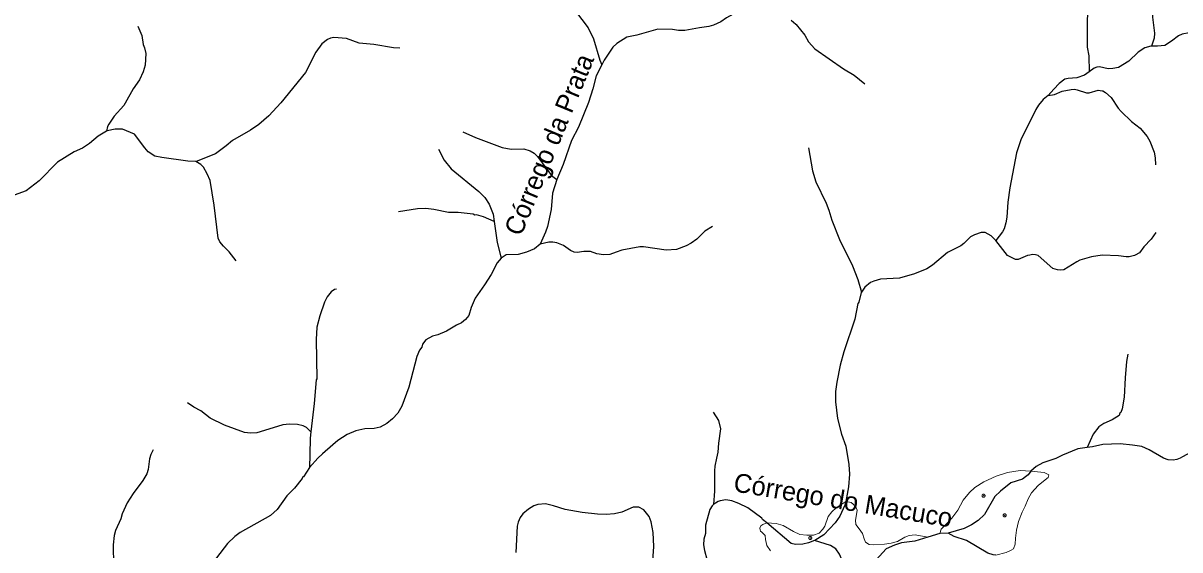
# Model space of a CAD drawing. Extents: x 396 to 422.2, y 7649.8 to 7677.6.
# Drawn here: x 409.11 to 415.26, y 7656.16 to 7658.96 of the extents above; entities that cross this region are included whole.
import ezdxf
from ezdxf.enums import TextEntityAlignment as Align

# ---------------------------------------------------------------- set-up
doc = ezdxf.new("R2010")
doc.units = 0
doc.header["$LTSCALE"] = 0.032
doc.header["$PDMODE"] = 32
doc.header["$PDSIZE"] = 0.016
doc.linetypes.add('SHORT_DASHED', pattern=[2.7, 1.5, -1.2])
doc.layers.add('21', color=7, linetype='SHORT_DASHED', lineweight=13)
doc.layers.add('7', color=7, linetype='Continuous', lineweight=25)
doc.layers.add('61', color=7, linetype='Continuous')

msp = doc.modelspace()

# ---------------------------------------------------------------- linework, layer by layer
at = {"layer": '21'}
for points in [[(413.9857, 7656.2498), (413.9939, 7656.2718), (414.0154, 7656.2949), (414.05, 7656.3312), (414.0814, 7656.3742), (414.1095, 7656.427), (414.1442, 7656.4666), (414.1722, 7656.4947), (414.2201, 7656.5244), (414.2862, 7656.5541), (414.3456, 7656.574), (414.4133, 7656.5839), (414.4702, 7656.5802)], [(414.4702, 7656.5802), (414.5404, 7656.574), (414.5619, 7656.5641), (414.5652, 7656.5607), (414.5619, 7656.5475), (414.5371, 7656.5277), (414.5091, 7656.5046), (414.4727, 7656.465), (414.4562, 7656.4336), (414.4397, 7656.3956), (414.4232, 7656.3626), (414.4034, 7656.3131), (414.3935, 7656.2668), (414.3885, 7656.2239), (414.3869, 7656.1925), (414.377, 7656.1678), (414.3654, 7656.1612), (414.339, 7656.148), (414.2845, 7656.1346)], [(413.0665, 7656.3055), (413.1155, 7656.3032), (413.1535, 7656.2916), (413.2079, 7656.2602), (413.2426, 7656.2437), (413.2789, 7656.2404), (413.3136, 7656.2404), (413.345, 7656.252), (413.3648, 7656.2718), (413.3747, 7656.2883), (413.3929, 7656.3395), (413.4127, 7656.3643), (413.4358, 7656.3857), (413.4589, 7656.4022), (413.4857, 7656.4188)], [(413.4857, 7656.4188), (413.5151, 7656.4138), (413.5382, 7656.3956), (413.5464, 7656.3742), (413.5415, 7656.3395), (413.5382, 7656.3197), (413.5398, 7656.2966), (413.558, 7656.2734), (413.5745, 7656.2487), (413.5844, 7656.2206), (413.591, 7656.2041), (413.6108, 7656.1909), (413.6339, 7656.1892), (413.6917, 7656.1925), (413.7281, 7656.1975), (413.7611, 7656.2074), (413.7991, 7656.2305), (413.8222, 7656.2388), (413.8552, 7656.2421), (413.9228, 7656.2307)], [(413.0858, 7656.1579), (413.0659, 7656.1859), (413.0593, 7656.2173), (413.0577, 7656.2388), (413.0395, 7656.2569), (413.0329, 7656.2619), (413.0313, 7656.2685), (413.0296, 7656.2784), (413.0346, 7656.29), (413.0445, 7656.2966), (413.0665, 7656.3055)]]:
    msp.add_lwpolyline(points, dxfattribs=at)
for p in [(414.2185, 7656.4501), (414.3307, 7656.3461), (413.2971, 7656.2256)]:
    msp.add_point(p, dxfattribs=at)
at = {"layer": '7'}
for points in [[(415.2069, 7659.5666), (415.2074, 7659.5654), (415.2074, 7659.538), (415.2002, 7659.4742), (415.2018, 7659.4284), (415.2207, 7659.3406), (415.221, 7659.3093), (415.2104, 7659.2632), (415.1962, 7659.2325), (415.1752, 7659.162), (415.1641, 7659.1337), (415.1295, 7659.0669), (415.1174, 7659.0318), (415.1165, 7658.9964), (415.1275, 7658.911), (415.1259, 7658.884), (415.1105, 7658.8421)], [(414.9434, 7659.4523), (414.9271, 7659.3901), (414.9116, 7659.3481), (414.8684, 7659.2841), (414.8571, 7659.2599), (414.8159, 7659.1949), (414.7961, 7659.1523), (414.7832, 7659.1093), (414.7696, 7658.988), (414.7695, 7658.8371), (414.7782, 7658.7899), (414.7807, 7658.7062)], [(411.8986, 7659.263), (411.9382, 7659.2113), (411.9814, 7659.1262), (412.0201, 7659.0645), (412.1172, 7658.9391), (412.1452, 7658.8813), (412.1788, 7658.7682), (412.1836, 7658.7545), (412.189, 7658.7424)], [(412.8866, 7659.012), (412.8515, 7658.9932), (412.8221, 7658.9721), (412.7821, 7658.953), (412.758, 7658.946), (412.708, 7658.9401), (412.6298, 7658.9244), (412.5975, 7658.9259), (412.5656, 7658.9314), (412.487, 7658.9322), (412.3758, 7658.8998), (412.3222, 7658.8902), (412.2686, 7658.8563), (412.247, 7658.8365), (412.2018, 7658.7676), (412.189, 7658.7424)], [(413.1952, 7658.9808), (413.2202, 7658.9588), (413.2223, 7658.957), (413.2688, 7658.9003), (413.2881, 7658.8651), (413.3214, 7658.827), (413.4737, 7658.7214), (413.5304, 7658.6872), (413.5869, 7658.6413)], [(409.723, 7658.9483), (409.7442, 7658.8988), (409.7515, 7658.8509), (409.7581, 7658.8339), (409.7643, 7658.8023), (409.7613, 7658.7408), (409.7517, 7658.7048), (409.731, 7658.6622), (409.6971, 7658.6148), (409.6552, 7658.5392), (409.6475, 7658.5254), (409.5974, 7658.4695), (409.5686, 7658.4262), (409.5618, 7658.4143), (409.5566, 7658.3901)], [(415.6395, 7658.878), (415.6009, 7658.887), (415.4837, 7658.926), (415.427, 7658.9354), (415.388, 7658.9362), (415.358, 7658.9288), (415.3334, 7658.9228), (415.3121, 7658.9133), (415.2735, 7658.9051), (415.2544, 7658.8972), (415.2176, 7658.8684), (415.1813, 7658.8463), (415.1435, 7658.8414), (415.1105, 7658.8421)], [(411.1146, 7658.8311), (411.0812, 7658.8338), (410.9763, 7658.851), (410.8996, 7658.8579), (410.8321, 7658.8826), (410.7641, 7658.8876), (410.7472, 7658.8844), (410.731, 7658.8772), (410.7005, 7658.8539), (410.6697, 7658.8097), (410.6134, 7658.7017), (410.4824, 7658.5399), (410.4187, 7658.4709), (410.3656, 7658.4244), (410.3222, 7658.3944), (410.2257, 7658.3399), (410.1918, 7658.311), (410.1346, 7658.2688), (410.032, 7658.2289), (410.0307, 7658.229)], [(415.1105, 7658.8421), (415.1077, 7658.8422), (415.0752, 7658.8334), (415.0405, 7658.8108), (414.9912, 7658.7617), (414.9356, 7658.7283), (414.9063, 7658.7225), (414.8811, 7658.7217), (414.8352, 7658.7313), (414.8205, 7658.7305), (414.8062, 7658.7257), (414.7807, 7658.7062)], [(412.189, 7658.7424), (412.159, 7658.6833), (412.1415, 7658.615), (412.1189, 7658.543), (412.0658, 7658.4112), (412.0286, 7658.3399), (411.9834, 7658.213), (411.9508, 7658.1322)], [(414.7807, 7658.7062), (414.7555, 7658.687), (414.7554, 7658.6869), (414.7149, 7658.6739), (414.6675, 7658.6697), (414.6504, 7658.666), (414.6201, 7658.6441), (414.5916, 7658.6124), (414.5626, 7658.5801)], [(414.5626, 7658.5801), (414.5955, 7658.5855), (414.6371, 7658.6021), (414.6842, 7658.6109), (414.7022, 7658.6125), (414.7168, 7658.6101), (414.766, 7658.5942), (414.7806, 7658.5942), (414.8269, 7658.607), (414.8496, 7658.6041), (414.8521, 7658.6038), (414.8672, 7658.5959), (414.8968, 7658.5697), (414.9349, 7658.5127), (414.9497, 7658.4952), (415.0055, 7658.4418), (415.0513, 7658.4049), (415.0874, 7658.3608), (415.102, 7658.3357), (415.1252, 7658.2788), (415.1315, 7658.2472), (415.1332, 7658.2098)], [(414.5626, 7658.5801), (414.5352, 7658.5576), (414.5113, 7658.5274), (414.4966, 7658.5042), (414.4927, 7658.4964), (414.4185, 7658.3493), (414.393, 7658.2743), (414.3579, 7658.0877), (414.3468, 7658.0124), (414.3428, 7657.9327), (414.3374, 7657.9019), (414.3276, 7657.8693), (414.3198, 7657.8535), (414.283, 7657.8076)], [(410.0307, 7658.229), (409.9888, 7658.2306), (409.8493, 7658.2495), (409.8121, 7658.2574), (409.7767, 7658.2802), (409.7602, 7658.3018), (409.705, 7658.3741), (409.6404, 7658.4003), (409.6022, 7658.4002), (409.5596, 7658.3919), (409.5566, 7658.3901)], [(409.5566, 7658.3901), (409.5118, 7658.3631), (409.4656, 7658.3248), (409.4286, 7658.3001), (409.384, 7658.2791), (409.2962, 7658.2244), (409.1978, 7658.1248), (409.1288, 7658.0721), (409.0448, 7658.0422), (409.0021, 7658.0315), (408.9914, 7658.0306), (408.9738, 7658.029), (408.9513, 7658.0319), (408.8741, 7658.0295), (408.8109, 7658.0191), (408.7832, 7658.0178)], [(411.4496, 7658.3869), (411.5169, 7658.3562), (411.6588, 7658.3035), (411.7064, 7658.2936), (411.7738, 7658.2951), (411.8082, 7658.2852), (411.8299, 7658.2719), (411.8464, 7658.2547), (411.9221, 7658.1537), (411.9508, 7658.1322)], [(411.3204, 7658.2944), (411.3511, 7658.2351), (411.3883, 7658.1889), (411.5354, 7658.0681), (411.5673, 7658.0362), (411.5908, 7658.0013), (411.6121, 7657.9489), (411.6175, 7657.9096)], [(413.2886, 7658.3007), (413.31, 7658.1786), (413.3263, 7658.1205), (413.3809, 7658.0067), (413.396, 7657.9688), (413.4113, 7657.917), (413.4531, 7657.8127), (413.5217, 7657.6727), (413.5508, 7657.5999), (413.5694, 7657.5329)], [(410.2456, 7657.6995), (410.209, 7657.7484), (410.1778, 7657.7772), (410.1592, 7657.8018), (410.15, 7657.8203), (410.1277, 7657.9968), (410.1064, 7658.1274), (410.0919, 7658.163), (410.0722, 7658.1988), (410.0569, 7658.2124), (410.0307, 7658.229)], [(411.9508, 7658.1322), (411.9273, 7658.0595), (411.9191, 7657.9738), (411.9002, 7657.8827), (411.8904, 7657.8529), (411.8621, 7657.7889)], [(411.6175, 7657.9096), (411.56, 7657.9339), (411.5226, 7657.944), (411.5139, 7657.942), (411.5058, 7657.9481), (411.4255, 7657.9569), (411.3736, 7657.9578), (411.2956, 7657.9729), (411.2532, 7657.9776), (411.2094, 7657.9768), (411.1082, 7657.9602)], [(411.6175, 7657.9096), (411.6329, 7657.7977), (411.6549, 7657.7145)], [(412.7782, 7657.8821), (412.7362, 7657.8582), (412.6942, 7657.8155), (412.664, 7657.7934), (412.6382, 7657.779), (412.5856, 7657.7599), (412.5309, 7657.7569), (412.4109, 7657.7751), (412.3921, 7657.7751), (412.2956, 7657.7567), (412.2656, 7657.7458), (412.2321, 7657.7337), (412.198, 7657.7313), (412.1632, 7657.7377), (412.1281, 7657.7496), (412.0928, 7657.7496), (412.0588, 7657.7449), (412.0422, 7657.7468), (412.023, 7657.7556), (411.9854, 7657.7819), (411.95, 7657.7955), (411.9292, 7657.7998), (411.9075, 7657.7984), (411.8621, 7657.7889)], [(414.283, 7657.8076), (414.2595, 7657.8329), (414.2276, 7657.8508), (414.2064, 7657.8508), (414.171, 7657.8388), (414.1493, 7657.8278), (414.1134, 7657.792), (414.0975, 7657.7801), (414.0272, 7657.7444), (413.9464, 7657.6762), (413.9161, 7657.657), (413.851, 7657.6302), (413.7723, 7657.6084), (413.6705, 7657.602), (413.6351, 7657.5923), (413.6179, 7657.5845), (413.5882, 7657.5595), (413.5694, 7657.5329)], [(415.134, 7657.851), (415.1102, 7657.8145), (415.0712, 7657.7745), (415.0467, 7657.7431), (415.024, 7657.7304), (415.0208, 7657.7286), (414.9932, 7657.7217), (414.9763, 7657.7209), (414.9361, 7657.7264), (414.8485, 7657.7296), (414.7915, 7657.7208), (414.7309, 7657.7032), (414.7139, 7657.6954), (414.6447, 7657.6522), (414.6283, 7657.65), (414.6119, 7657.6515), (414.5869, 7657.6595), (414.5082, 7657.7286), (414.4948, 7657.7325), (414.4785, 7657.7328), (414.4652, 7657.7306), (414.4512, 7657.7282), (414.4023, 7657.7073), (414.3882, 7657.7066), (414.3461, 7657.7282), (414.283, 7657.8076)], [(411.8621, 7657.7889), (411.8312, 7657.763), (411.7881, 7657.7455), (411.745, 7657.7336), (411.6804, 7657.7319), (411.6549, 7657.7145)], [(411.6549, 7657.7145), (411.6544, 7657.7142), (411.6324, 7657.6885), (411.601, 7657.627), (411.5656, 7657.5716), (411.5159, 7657.5019), (411.4947, 7657.4519), (411.4826, 7657.4087), (411.4652, 7657.3874), (411.4432, 7657.3704), (411.4163, 7657.3574), (411.3627, 7657.325), (411.3168, 7657.3067), (411.2887, 7657.2998), (411.2538, 7657.2796), (411.2365, 7657.2568), (411.2326, 7657.2404), (411.2208, 7657.2247), (411.2049, 7657.1905), (411.1626, 7657.028), (411.1264, 7656.9263), (411.1042, 7656.8894), (411.0768, 7656.8586), (411.047, 7656.8342), (411.0109, 7656.8155), (410.9796, 7656.8079), (410.93, 7656.8069)], [(410.7791, 7657.5493), (410.7681, 7657.5467), (410.7512, 7657.5352), (410.7295, 7657.509), (410.7153, 7657.4807), (410.6902, 7657.4082), (410.6738, 7657.3474), (410.6703, 7657.2822), (410.6736, 7657.0722), (410.6707, 7657.0663), (410.6607, 7656.9409), (410.643, 7656.7909)], [(413.5694, 7657.5329), (413.5682, 7657.5312), (413.5552, 7657.4806), (413.5515, 7657.4739), (413.5509, 7657.4728), (413.5345, 7657.3893), (413.4762, 7657.216), (413.4563, 7657.1448), (413.4376, 7657.0542), (413.432, 7657.0044), (413.4314, 7656.9497), (413.4412, 7656.862), (413.4634, 7656.7775), (413.4856, 7656.7141), (413.503, 7656.6171), (413.5062, 7656.5645), (413.4998, 7656.4972), (413.4857, 7656.4188), (413.4802, 7656.4006)], [(414.9849, 7657.2034), (414.9785, 7657.1646), (414.9704, 7657.0781), (414.9656, 7656.9745), (414.9555, 7656.913), (414.948, 7656.8926), (414.943, 7656.8894), (414.9389, 7656.877), (414.9015, 7656.8547), (414.8575, 7656.835), (414.8307, 7656.8163), (414.8007, 7656.7777), (414.7688, 7656.7068)], [(410.643, 7656.7909), (410.6193, 7656.8125), (410.6017, 7656.8221), (410.5722, 7656.83), (410.5281, 7656.8316), (410.4933, 7656.8269), (410.4887, 7656.8255), (410.3548, 7656.7855), (410.3219, 7656.7831), (410.2904, 7656.7871), (410.1825, 7656.8255), (410.1065, 7656.8631), (410.0573, 7656.9016), (410.0204, 7656.9215), (409.987, 7656.945)], [(412.7814, 7656.894), (412.8093, 7656.8513), (412.8204, 7656.8069), (412.8093, 7656.7307), (412.8059, 7656.6818), (412.7991, 7656.65), (412.7901, 7656.6079), (412.7878, 7656.5836), (412.7885, 7656.4739), (412.7824, 7656.4039)], [(410.93, 7656.8069), (410.8818, 7656.7963), (410.8349, 7656.7768), (410.7862, 7656.7442), (410.718, 7656.6863), (410.7038, 7656.6727), (410.6797, 7656.6496), (410.6352, 7656.6006), (410.6349, 7656.6002)], [(410.643, 7656.7909), (410.639, 7656.757), (410.6367, 7656.6688), (410.6349, 7656.6002)], [(415.8132, 7656.7767), (415.788, 7656.7392), (415.766, 7656.7223), (415.7457, 7656.7135), (415.698, 7656.7081), (415.655, 7656.7105), (415.5565, 7656.7088), (415.4416, 7656.716), (415.419, 7656.7137), (415.3751, 7656.7012), (415.3188, 7656.6804), (415.2769, 7656.6573), (415.2637, 7656.6501), (415.2467, 7656.6437), (415.226, 7656.6403), (415.1998, 7656.6419), (415.1749, 7656.6497), (415.0995, 7656.695), (415.0604, 7656.7117), (415.01, 7656.7201), (414.944, 7656.7256), (414.8533, 7656.7231), (414.7985, 7656.7113), (414.7688, 7656.7068)], [(409.8043, 7656.6946), (409.791, 7656.6689), (409.7845, 7656.6465), (409.7771, 7656.5897), (409.7704, 7656.5671), (409.7494, 7656.5321), (409.6976, 7656.4627), (409.6654, 7656.4129), (409.6394, 7656.3547), (409.6319, 7656.3281), (409.6035, 7656.2649), (409.5969, 7656.2391), (409.5906, 7656.1891), (409.5938, 7656.0784), (409.6002, 7656.0219), (409.6225, 7655.9433), (409.624, 7655.9098), (409.6179, 7655.872)], [(414.7688, 7656.7068), (414.72, 7656.6993), (414.6387, 7656.6666), (414.6029, 7656.6488), (414.5331, 7656.6258), (414.4977, 7656.6054), (414.4702, 7656.5802)], [(410.6349, 7656.6002), (410.6027, 7656.5501), (410.6, 7656.5506), (410.5967, 7656.5421), (410.5554, 7656.4912), (410.5149, 7656.4492), (410.4637, 7656.3779), (410.4272, 7656.3448), (410.2668, 7656.2547), (410.2375, 7656.2342), (410.2, 7656.1964), (410.1399, 7656.12), (410.1127, 7656.0776), (410.1022, 7656.0384), (410.0814, 7655.9254), (410.0586, 7655.8798), (410.0128, 7655.8262), (409.9816, 7655.7845)], [(414.4702, 7656.5802), (414.4557, 7656.5619), (414.4413, 7656.5502), (414.4262, 7656.538), (414.3633, 7656.5185), (414.3087, 7656.4748), (414.2776, 7656.4462), (414.2234, 7656.3503), (414.1902, 7656.3179), (414.1547, 7656.2947), (414.1155, 7656.2768), (414.0302, 7656.2508)], [(412.4611, 7656.1045), (412.4663, 7656.18), (412.4616, 7656.2548), (412.4512, 7656.3122), (412.4407, 7656.3404), (412.412, 7656.3747), (412.3861, 7656.389), (412.3558, 7656.3898), (412.2962, 7656.3631), (412.2569, 7656.3531), (412.212, 7656.3508), (412.1668, 7656.3523), (412.084, 7656.3617), (411.9939, 7656.3772), (411.9317, 7656.3971), (411.8905, 7656.4066), (411.8494, 7656.4035), (411.828, 7656.3961), (411.7985, 7656.3785), (411.7688, 7656.3542), (411.7548, 7656.3345), (411.7447, 7656.3097), (411.7396, 7656.2876), (411.7323, 7656.148)], [(412.7824, 7656.4039), (412.7752, 7656.3967), (412.7632, 7656.3764), (412.7407, 7656.2937), (412.7406, 7656.2491), (412.7311, 7656.2184), (412.7302, 7656.1897), (412.7342, 7656.1594), (412.7469, 7656.1123), (412.7494, 7656.0809), (412.7438, 7656.0525), (412.7342, 7656.0238), (412.7264, 7655.9814), (412.7374, 7655.9201), (412.7341, 7655.8787), (412.7151, 7655.8515), (412.6816, 7655.8271), (412.6802, 7655.8271)], [(413.0665, 7656.3055), (413.0437, 7656.3246), (413.04, 7656.3311), (412.9656, 7656.3864), (412.9182, 7656.4092), (412.8803, 7656.4235), (412.8488, 7656.4281), (412.818, 7656.4235), (412.8084, 7656.4193), (412.794, 7656.4111), (412.7824, 7656.4039)], [(413.4802, 7656.4006), (413.4549, 7656.3409), (413.4298, 7656.3062), (413.3699, 7656.2414), (413.3218, 7656.2121), (413.32, 7656.2114)], [(413.32, 7656.2114), (413.2882, 7656.1996), (413.2578, 7656.1923), (413.2183, 7656.1915), (413.1965, 7656.1966), (413.0665, 7656.3055)], [(414.0302, 7656.2508), (413.9857, 7656.2498), (413.9228, 7656.2307)], [(414.2845, 7656.1346), (414.2699, 7656.1363), (414.2419, 7656.1441), (414.1271, 7656.213), (414.063, 7656.2338), (414.0302, 7656.2508)], [(413.9228, 7656.2307), (413.8529, 7656.2094), (413.7829, 7656.1996), (413.7457, 7656.1866), (413.7015, 7656.1669), (413.6468, 7656.1099), (413.6203, 7656.0572), (413.5822, 7656.0083), (413.5513, 7655.991), (413.5334, 7655.9885), (413.5117, 7655.9945), (413.4901, 7656.0186), (413.4758, 7656.0416), (413.4635, 7656.1151), (413.4526, 7656.1387), (413.4335, 7656.1669), (413.4043, 7656.1849), (413.32, 7656.2114)]]:
    msp.add_lwpolyline(points, dxfattribs=at)

# ---------------------------------------------------------------- texts
at = {"layer": '61'}
for s, rotation, p in [('Córrego da Prata', 67.596, (411.9548, 7658.2999)), ('Córrego do Macuco', 350.534, (413.4636, 7656.3778))]:
    msp.add_text(s, height=0.1, rotation=rotation, dxfattribs=at).set_placement(p, align=Align.CENTER)

doc.saveas('drawing.dxf')
